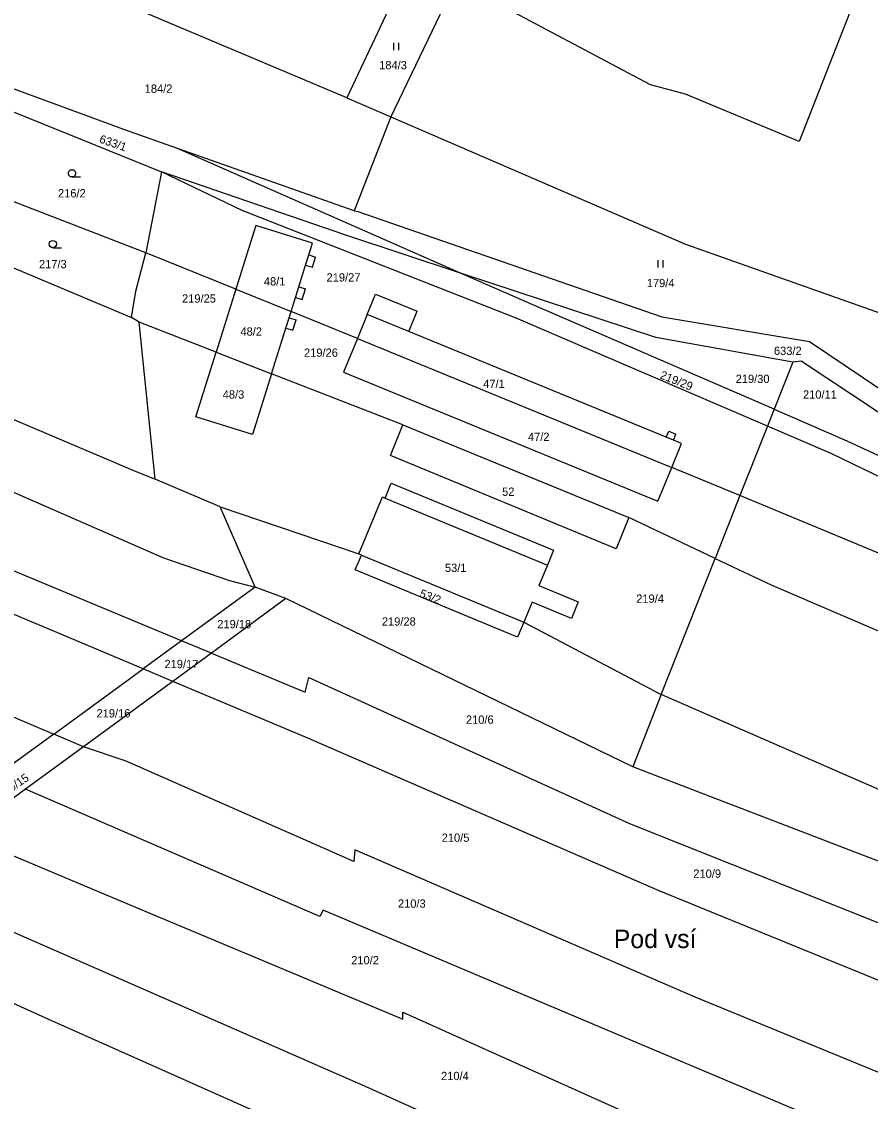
# Model space of a CAD drawing. Extents: x -746176 to -739709, y -1128407 to -1124482.
# Drawn here: x -742917.8 to -742743.6, y -1127796.2 to -1127574.6 of the extents above; entities that cross this region are included whole.
import ezdxf

# ---------------------------------------------------------------- set-up
doc = ezdxf.new("R2010")
doc.units = 0
for name, color, linetype in [('Vrstva 33', 7, 'Continuous'), ('Vrstva 42', 7, 'Continuous'), ('Vrstva 43', 7, 'Continuous'), ('Vrstva 44', 7, 'Continuous'), ('Vrstva 47', 7, 'Continuous')]:
    doc.layers.add(name, color=color, linetype=linetype)

msp = doc.modelspace()

# ---------------------------------------------------------------- linework, layer by layer
at = {"layer": 'Vrstva 33'}
for p, q in [((-742839.05, -1127564.77), (-742851.05, -1127590.28)), ((-742829.14, -1127567.37), (-742842.01, -1127594.12)), ((-742851.05, -1127590.28), (-742842.01, -1127594.12)), ((-742919.33, -1127593.19), (-742889.07, -1127605.41)), ((-742842.01, -1127594.12), (-742849.54, -1127613.47)), ((-742827.7, -1127626.22), (-742885.79, -1127600.64)), ((-742849.54, -1127613.47), (-742885.79, -1127600.64)), ((-742889.07, -1127605.41), (-742892.31, -1127622.04)), ((-742892.31, -1127622.04), (-742925.74, -1127609.17)), ((-742873.81, -1127629.53), (-742892.31, -1127622.04)), ((-742873.81, -1127629.53), (-742877.87, -1127642.45)), ((-742873.81, -1127629.53), (-742862.47, -1127634.12)), ((-742893.68, -1127636.29), (-742895.2, -1127635.33)), ((-742848.87, -1127639.63), (-742862.47, -1127634.12)), ((-742890.34, -1127668.53), (-742893.68, -1127636.29)), ((-742877.87, -1127642.45), (-742893.68, -1127636.29)), ((-742848.87, -1127639.63), (-742784.35, -1127666.12)), ((-742877.87, -1127642.45), (-742866.48, -1127646.88)), ((-742759.53, -1127644.48), (-742763.36, -1127654.17)), ((-742839.52, -1127657.38), (-742866.48, -1127646.88)), ((-742763.36, -1127654.17), (-742764.73, -1127657.63)), ((-742839.52, -1127657.38), (-742793.13, -1127676.4)), ((-742764.73, -1127657.63), (-742770.35, -1127671.87)), ((-742770.35, -1127671.87), (-742784.35, -1127666.12)), ((-742877.02, -1127674.2), (-742890.34, -1127668.53)), ((-742770.35, -1127671.87), (-742775.45, -1127684.77)), ((-742877.02, -1127674.2), (-742848.58, -1127683.87)), ((-742869.86, -1127690.69), (-742877.02, -1127674.2)), ((-742775.45, -1127684.77), (-742793.13, -1127676.4)), ((-742848.05, -1127684.09), (-742848.58, -1127683.87)), ((-742848.05, -1127684.09), (-742814.73, -1127697.87)), ((-742786.49, -1127712.73), (-742775.45, -1127684.77)), ((-742869.86, -1127690.69), (-742884.93, -1127701.69)), ((-742863.54, -1127693.04), (-742869.86, -1127690.69)), ((-742863.54, -1127693.04), (-742878.82, -1127704.23)), ((-742792.35, -1127727.57), (-742863.54, -1127693.04)), ((-742814.73, -1127697.87), (-742786.49, -1127712.73)), ((-742962.09, -1127699.23), (-742911.19, -1127720.85)), ((-742884.93, -1127701.69), (-742892.82, -1127707.45)), ((-742878.82, -1127704.23), (-742884.93, -1127701.69)), ((-742878.82, -1127704.23), (-742886.72, -1127710.02)), ((-742911.19, -1127720.85), (-742892.82, -1127707.45)), ((-742886.72, -1127710.02), (-742892.82, -1127707.45)), ((-742886.72, -1127710.02), (-742905.07, -1127723.45)), ((-742786.49, -1127712.73), (-742792.35, -1127727.57)), ((-742911.19, -1127720.85), (-742935.96, -1127738.92)), ((-742905.07, -1127723.45), (-742911.19, -1127720.85)), ((-742905.07, -1127723.45), (-742916.95, -1127732.14)), ((-742663.65, -1127776.96), (-742792.35, -1127727.57)), ((-742916.95, -1127732.14), (-742929.76, -1127741.52))]:
    msp.add_line(p, q, dxfattribs=at)
for points in [[(-742743.76, -1127562.35), (-742758.22, -1127599.23), (-742781.54, -1127589.48), (-742788.73, -1127587.57), (-742823.54, -1127569.02), (-742829.14, -1127567.37)], [(-742851.05, -1127590.28), (-742889.01, -1127574.21), (-742909.93, -1127565.28)], [(-742885.79, -1127600.64), (-742896.8, -1127596.74), (-742927.53, -1127585.44)], [(-742842.01, -1127594.12), (-742781.53, -1127620.27), (-742738.25, -1127635.58), (-742671.97, -1127665.27), (-742626.86, -1127683.46)], [(-742764.73, -1127657.63), (-742816.28, -1127635.5), (-742872.48, -1127613.38), (-742889.07, -1127605.41)], [(-742827.7, -1127626.22), (-742851.21, -1127618.45), (-742889.07, -1127605.41)], [(-742849.54, -1127613.47), (-742848.76, -1127613.6), (-742786.4, -1127635.17), (-742756.11, -1127640.29), (-742704.21, -1127675.14), (-742663.56, -1127694.46), (-742647.49, -1127700.26), (-742632.48, -1127703.04)], [(-742862.47, -1127634.12), (-742861.56, -1127631.22), (-742860.87, -1127629.02), (-742859.48, -1127624.6), (-742858.82, -1127622.5), (-742858.07, -1127620.11), (-742869.71, -1127616.46), (-742873.81, -1127629.53)], [(-742933.59, -1127619.25), (-742932.84, -1127619.53), (-742895.2, -1127635.33)], [(-742895.2, -1127635.33), (-742894.34, -1127629.94), (-742892.31, -1127622.04)], [(-742759.53, -1127644.48), (-742787.62, -1127639.47), (-742827.7, -1127626.22)], [(-742763.36, -1127654.17), (-742813.01, -1127632.69), (-742827.7, -1127626.22)], [(-742966.93, -1127635.29), (-742957.86, -1127639.93), (-742940.86, -1127647.2), (-742894.92, -1127666.66), (-742890.34, -1127668.53)], [(-742866.48, -1127646.88), (-742863.54, -1127637.53), (-742862.87, -1127635.39), (-742862.47, -1127634.12)], [(-742784.35, -1127666.12), (-742782.33, -1127661.21), (-742783.99, -1127660.53), (-742785.47, -1127659.92), (-742838.33, -1127638.19), (-742846.84, -1127634.7), (-742848.87, -1127639.63)], [(-742989.43, -1127637.82), (-742962.79, -1127651.94), (-742947.37, -1127659.01), (-742888.66, -1127684.65), (-742875.08, -1127689.31), (-742869.86, -1127690.69)], [(-742848.87, -1127639.63), (-742851.71, -1127646.54), (-742787.2, -1127673.06), (-742784.35, -1127666.12)], [(-742866.48, -1127646.88), (-742870.4, -1127659.37), (-742882.04, -1127655.72), (-742877.87, -1127642.45)], [(-742664.42, -1127698.33), (-742705.7, -1127678.8), (-742757.77, -1127644.27), (-742759.53, -1127644.48)], [(-742884.93, -1127701.69), (-742931.01, -1127682.52), (-742982.33, -1127658.51), (-742997.69, -1127649.67)], [(-742763.36, -1127654.17), (-742748.4, -1127660.64), (-742692.32, -1127686.56), (-742664.42, -1127698.33)], [(-742892.82, -1127707.45), (-742959.07, -1127679.57), (-742986.2, -1127666.67), (-743003.07, -1127657.38)], [(-742793.13, -1127676.4), (-742795.78, -1127682.8), (-742842.1, -1127663.63), (-742839.52, -1127657.38)], [(-742640.13, -1127711.82), (-742707.48, -1127684.6), (-742751.48, -1127663.32), (-742764.73, -1127657.63)], [(-742848.58, -1127683.87), (-742843.74, -1127672.16), (-742843.19, -1127672.39), (-742841.94, -1127669.37), (-742808.61, -1127683.09), (-742809.88, -1127686.17), (-742811.62, -1127690.36), (-742803.55, -1127693.7), (-742804.94, -1127697.11), (-742813.02, -1127693.76), (-742814.73, -1127697.87)], [(-742643.36, -1127725.63), (-742711.98, -1127696.17), (-742770.35, -1127671.87)], [(-742814.73, -1127697.87), (-742816.01, -1127700.98), (-742849.31, -1127687.14), (-742848.05, -1127684.09)], [(-742775.45, -1127684.77), (-742763.82, -1127690.28), (-742650.2, -1127739.03)], [(-742878.82, -1127704.23), (-742859.56, -1127712.24), (-742858.85, -1127709.24), (-742793.05, -1127739.22), (-742667.79, -1127789.16)], [(-742691.75, -1127791.9), (-742786.9, -1127753.03), (-742859.54, -1127721.45), (-742886.72, -1127710.02)], [(-742659.43, -1127765.34), (-742739.02, -1127733.43), (-742786.49, -1127712.73)], [(-742697.57, -1127810.08), (-742723.74, -1127797.75), (-742779.52, -1127774.85), (-742849.36, -1127744.61), (-742849.6, -1127747), (-742896.29, -1127726.42), (-742905.07, -1127723.45)], [(-742705.33, -1127822.31), (-742752.11, -1127800.85), (-742855.88, -1127756.96), (-742856.57, -1127758.28), (-742916.95, -1127732.14)], [(-742929.76, -1127741.52), (-742892.25, -1127757.26), (-742839.56, -1127779.37), (-742839.56, -1127777.92), (-742777.16, -1127805.95), (-742712.92, -1127837.01)], [(-742942.9, -1127751.14), (-742921.78, -1127760.46), (-742847.12, -1127793.15), (-742812.02, -1127809), (-742724.3, -1127849.19), (-742701.43, -1127856.81), (-742666.84, -1127871.89)], [(-742670.28, -1127883.77), (-742733.59, -1127858.01), (-742796.71, -1127830.89), (-742912.22, -1127779.41), (-742955.04, -1127760.03)]]:
    msp.add_lwpolyline(points, dxfattribs=at)
at = {"layer": 'Vrstva 44'}
for p, q in [((-742841.37, -1127580.49), (-742841.37, -1127578.99)), ((-742840.37, -1127580.49), (-742840.37, -1127578.99)), ((-742907.43, -1127606.5), (-742905.68, -1127606.5)), ((-742911.36, -1127621.01), (-742909.61, -1127621.01)), ((-742787.11, -1127625.1), (-742787.11, -1127623.6)), ((-742786.11, -1127625.1), (-742786.11, -1127623.6))]:
    msp.add_line(p, q, dxfattribs=at)
for centre in [(-742907.43, -1127605.75), (-742911.36, -1127620.26)]:
    msp.add_circle(centre, 0.75, dxfattribs=at)
at = {"layer": 'Vrstva 47'}
for p, q in [((-742858.82, -1127622.5), (-742857.45, -1127622.93)), ((-742859.48, -1127624.6), (-742858.11, -1127625.03)), ((-742858.11, -1127625.03), (-742857.45, -1127622.93)), ((-742860.87, -1127629.02), (-742859.49, -1127629.46)), ((-742861.56, -1127631.22), (-742860.18, -1127631.65)), ((-742860.18, -1127631.65), (-742859.49, -1127629.46)), ((-742846.84, -1127634.7), (-742845.14, -1127630.56)), ((-742845.14, -1127630.56), (-742836.62, -1127634.03)), ((-742862.87, -1127635.39), (-742861.43, -1127635.84)), ((-742862.11, -1127637.97), (-742861.43, -1127635.84)), ((-742838.33, -1127638.19), (-742836.62, -1127634.03)), ((-742863.54, -1127637.53), (-742862.11, -1127637.97)), ((-742785.47, -1127659.92), (-742784.96, -1127658.67)), ((-742784.96, -1127658.67), (-742783.48, -1127659.28)), ((-742783.99, -1127660.53), (-742783.48, -1127659.28)), ((-742843.19, -1127672.39), (-742809.88, -1127686.17))]:
    msp.add_line(p, q, dxfattribs=at)

# ---------------------------------------------------------------- texts
at = {"layer": 'Vrstva 42'}
for s, p in [('184/3', (-742844.4, -1127584.39)), ('184/2', (-742892.51, -1127589.21)), ('216/2', (-742910.31, -1127610.69)), ('217/3', (-742914.21, -1127625.23)), ('48/1', (-742868.05, -1127628.76)), ('219/27', (-742855.19, -1127627.95)), ('179/4', (-742789.47, -1127629.11)), ('219/25', (-742884.85, -1127632.29)), ('48/2', (-742872.87, -1127639.07)), ('219/26', (-742859.82, -1127643.4)), ('633/2', (-742763.38, -1127643.03)), ('47/1', (-742823.05, -1127649.81)), ('219/30', (-742771.24, -1127648.78)), ('48/3', (-742876.5, -1127651.98)), ('210/11', (-742757.42, -1127652)), ('47/2', (-742813.86, -1127660.68)), ('52', (-742819.16, -1127671.94)), ('53/1', (-742830.9, -1127687.56)), ('219/4', (-742791.64, -1127693.89)), ('219/18', (-742877.62, -1127699.12)), ('219/28', (-742843.84, -1127698.57)), ('219/17', (-742888.45, -1127707.31)), ('219/16', (-742902.4, -1127717.43)), ('210/6', (-742826.59, -1127718.72)), ('210/5', (-742831.56, -1127742.95)), ('210/9', (-742779.92, -1127750.33)), ('210/3', (-742840.54, -1127756.47)), ('210/2', (-742850.13, -1127768.1)), ('210/4', (-742831.69, -1127791.86))]:
    msp.add_text(s, height=1.7, dxfattribs=at).set_placement(p)
for s, rotation, p in [('633/1', 341, (-742901.96, -1127599.4)), ('219/29', 338, (-742786.91, -1127647.77)), ('53/2', 339, (-742836.26, -1127692.63)), ('219/15', 34, (-742921.86, -1127734.11))]:
    msp.add_text(s, height=1.7, rotation=rotation, dxfattribs=at).set_placement(p)
at = {"layer": 'Vrstva 43'}
msp.add_text('Pod vsí', height=3.8, dxfattribs=at).set_placement((-742796.24, -1127764.76))

doc.saveas('drawing.dxf')
